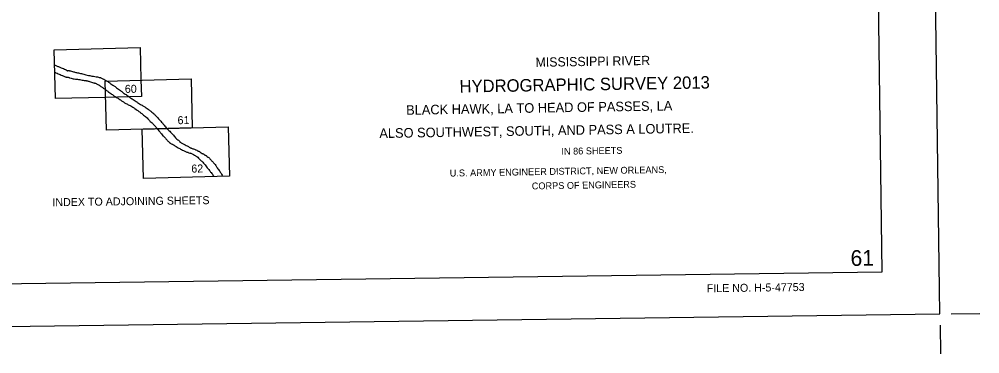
# Model space of a CAD drawing. Extents: x 3753511 to 3791668, y 379550 to 405377.
# Drawn here: x 3777627 to 3791668, y 380046 to 384938 of the extents above; entities that cross this region are included whole.
import ezdxf

# ---------------------------------------------------------------- set-up
doc = ezdxf.new("R2010")
doc.units = 0
for name, color, linetype in [('G-ANNO-NPLT', 7, 'Continuous'), ('V-ANNO-DIMS', 7, 'Continuous'), ('V-ANNO-NPLT', 7, 'Continuous'), ('V-ANNO-SYMB', 7, 'Continuous'), ('V-ANNO-TEXT', 7, 'Continuous')]:
    doc.layers.add(name, color=color, linetype=linetype)

msp = doc.modelspace()

# ---------------------------------------------------------------- linework, layer by layer
at = {"layer": 'G-ANNO-NPLT'}
msp.add_lwpolyline([(3754421, 380133), (3791084, 380629), (3790758, 404794), (3754094, 404298)], close=True, dxfattribs=at)
at = {"layer": 'V-ANNO-DIMS'}
for p, q in [((3791251, 380631), (3791668, 380637)), ((3791087, 380463), (3791092, 380046))]:
    msp.add_line(p, q, dxfattribs=at)
at = {"layer": 'V-ANNO-NPLT'}
for points in [[(3778156, 383777), (3778138, 384491), (3779393, 384525), (3779405, 384054)], [(3778902, 383314), (3778883, 384032), (3780138, 384066), (3780156, 383348)], [(3779405, 384050), (3779412, 383807)], [(3778879, 383794), (3778156, 383777)], [(3779412, 383807), (3778886, 383794)], [(3780156, 383348), (3778902, 383314)], [(3779444, 382610), (3779425, 383328), (3780680, 383363), (3780700, 382645)], [(3780700, 382645), (3779444, 382610)]]:
    msp.add_lwpolyline(points, dxfattribs=at)
for points in [[(3778144, 384268), (3778161, 384261), (3778201, 384244), (3778238, 384228), (3778274, 384215), (3778302, 384203), (3778326, 384188), (3778331, 384185), (3778336, 384184), (3778342, 384186), (3778343, 384189), (3778349, 384189), (3778361, 384185), (3778375, 384182), (3778408, 384173), (3778429, 384168)], [(3778147, 384163), (3778164, 384155), (3778198, 384140), (3778224, 384129), (3778260, 384114), (3778264, 384112)], [(3778429, 384168), (3778453, 384161), (3778507, 384149), (3778536, 384143), (3778569, 384134)], [(3778264, 384112), (3778290, 384099), (3778307, 384093), (3778319, 384089), (3778322, 384090), (3778326, 384090), (3778334, 384089), (3778350, 384085), (3778354, 384083), (3778357, 384084), (3778361, 384083), (3778368, 384081), (3778400, 384071), (3778430, 384066), (3778465, 384061), (3778494, 384057), (3778563, 384046)], [(3778563, 384046), (3778588, 384042), (3778596, 384041), (3778604, 384040), (3778620, 384036), (3778634, 384033), (3778653, 384028), (3778682, 384019), (3778714, 384009), (3778720, 384007), (3778725, 384005), (3778732, 384003), (3778751, 383997), (3778756, 383994), (3778777, 383983), (3778790, 383977), (3778802, 383969)], [(3778569, 384134), (3778602, 384124), (3778641, 384116), (3778674, 384110), (3778707, 384103), (3778715, 384103), (3778751, 384095), (3778755, 384094), (3778759, 384096), (3778761, 384097), (3778765, 384097), (3778769, 384095), (3778772, 384094), (3778795, 384085), (3778797, 384084), (3778803, 384084), (3778805, 384084), (3778810, 384084), (3778813, 384084), (3778818, 384082), (3778839, 384071)], [(3778839, 384071), (3778857, 384061), (3778861, 384061), (3778864, 384060), (3778877, 384052), (3778905, 384036), (3778934, 384017), (3778966, 383994), (3778994, 383975)], [(3778802, 383969), (3778839, 383943), (3778871, 383920), (3778904, 383896)], [(3778904, 383896), (3778936, 383872), (3778965, 383852), (3778989, 383836), (3779011, 383819)], [(3778994, 383975), (3779029, 383952), (3779050, 383935), (3779078, 383914), (3779105, 383895), (3779127, 383880)], [(3779011, 383819), (3779031, 383807), (3779046, 383798)], [(3779046, 383798), (3779073, 383782), (3779096, 383765), (3779133, 383740), (3779165, 383717), (3779209, 383694), (3779260, 383669), (3779289, 383654), (3779302, 383642)], [(3779127, 383880), (3779161, 383852), (3779188, 383835), (3779213, 383817), (3779235, 383803)], [(3779235, 383803), (3779277, 383772), (3779335, 383734), (3779370, 383710), (3779401, 383692)], [(3779302, 383642), (3779319, 383630), (3779350, 383609), (3779384, 383583), (3779418, 383557), (3779445, 383536), (3779471, 383513)], [(3779401, 383692), (3779442, 383667), (3779481, 383642), (3779512, 383622), (3779550, 383591), (3779578, 383570), (3779603, 383547)], [(3779471, 383513), (3779517, 383472), (3779543, 383442), (3779569, 383421), (3779587, 383402)], [(3779603, 383547), (3779632, 383517), (3779652, 383495), (3779696, 383445), (3779719, 383421)], [(3779587, 383402), (3779615, 383373), (3779646, 383334)], [(3779645, 383334), (3779658, 383319), (3779681, 383292), (3779706, 383261), (3779728, 383235), (3779755, 383207), (3779772, 383188)], [(3779719, 383421), (3779744, 383388), (3779788, 383338)], [(3779788, 383338), (3779813, 383312), (3779840, 383285), (3779863, 383260), (3779881, 383240), (3779900, 383218)], [(3779772, 383188), (3779793, 383164), (3779824, 383137), (3779850, 383118)], [(3779900, 383218), (3779921, 383194), (3779943, 383175), (3779963, 383159), (3779972, 383150)], [(3779850, 383118), (3779883, 383100), (3779920, 383077), (3779949, 383059), (3779998, 383033)], [(3779972, 383150), (3779996, 383132), (3780035, 383109), (3780066, 383093), (3780100, 383076)], [(3780100, 383076), (3780104, 383073), (3780123, 383060), (3780131, 383056), (3780136, 383056), (3780138, 383056), (3780142, 383054), (3780165, 383044), (3780187, 383036), (3780196, 383030), (3780200, 383031), (3780203, 383030), (3780209, 383028), (3780235, 383013)], [(3779998, 383033), (3780028, 383016), (3780068, 383000), (3780084, 382993), (3780090, 382992), (3780097, 382991), (3780119, 382979), (3780122, 382980), (3780123, 382982), (3780125, 382981), (3780126, 382981), (3780137, 382977), (3780157, 382968), (3780190, 382951)], [(3780190, 382951), (3780204, 382942), (3780222, 382929), (3780248, 382908), (3780270, 382883)], [(3780235, 383013), (3780241, 383011), (3780244, 383010), (3780247, 383008), (3780248, 383009), (3780248, 383010), (3780250, 383009), (3780252, 383008), (3780253, 383008), (3780273, 382993), (3780302, 382976), (3780311, 382971), (3780315, 382971), (3780319, 382970), (3780341, 382952), (3780344, 382951), (3780346, 382951), (3780350, 382950), (3780355, 382946), (3780371, 382932)], [(3780371, 382932), (3780381, 382924), (3780385, 382923), (3780424, 382885), (3780453, 382855), (3780480, 382825)], [(3780270, 382883), (3780280, 382875), (3780297, 382861), (3780322, 382833), (3780344, 382807)], [(3780344, 382807), (3780365, 382779), (3780387, 382751), (3780406, 382727)], [(3780480, 382825), (3780499, 382798), (3780522, 382764), (3780538, 382740)], [(3780406, 382727), (3780431, 382696), (3780468, 382646), (3780473, 382639)], [(3780538, 382740), (3780558, 382714), (3780572, 382690), (3780592, 382658), (3780603, 382642)]]:
    msp.add_spline(points, degree=3, dxfattribs=at)
at = {"layer": 'V-ANNO-SYMB'}
msp.add_lwpolyline([(3757162, 380796), (3790243, 381243), (3789933, 404157), (3756853, 403710), (3757162, 380796)], dxfattribs=at)

# ---------------------------------------------------------------- texts
at = {"layer": 'V-ANNO-NPLT'}
for s, height, p in [('60', 117, (3779171, 383860)), ('61', 117, (3779942, 383402)), ('62', 117, (3780143, 382695)), ('INDEX TO ADJOINING SHEETS', 116.66, (3778112, 382203))]:
    msp.add_text(s, height=height, rotation=0.7747, dxfattribs=at).set_placement(p)
at = {"layer": 'V-ANNO-TEXT'}
for s, height, rotation, p in [('MISSISSIPPI RIVER', 135, 0.9505, (3785175, 384241)), ('HYDROGRAPHIC SURVEY 2013', 181.7, 0.9505, (3784064, 383865)), ('BLACK HAWK, LA TO HEAD OF PASSES, LA', 140, 0.9505, (3783284, 383540)), ('ALSO SOUTHWEST, SOUTH, AND PASS A LOUTRE.', 140, 0.9505, (3782892, 383200)), ('IN 86 SHEETS', 100, 0.9505, (3785553, 382956)), ('U.S. ARMY ENGINEER DISTRICT, NEW ORLEANS,', 100, 0.9505, (3783921, 382637)), ('CORPS OF ENGINEERS', 100, 0.9505, (3785120, 382449)), ('61', 230, 0.7747, (3789780, 381330)), ('FILE NO. H-5-47753', 116.66, 0.7747, (3787677, 380945))]:
    msp.add_text(s, height=height, rotation=rotation, dxfattribs=at).set_placement(p)

doc.saveas('drawing.dxf')
